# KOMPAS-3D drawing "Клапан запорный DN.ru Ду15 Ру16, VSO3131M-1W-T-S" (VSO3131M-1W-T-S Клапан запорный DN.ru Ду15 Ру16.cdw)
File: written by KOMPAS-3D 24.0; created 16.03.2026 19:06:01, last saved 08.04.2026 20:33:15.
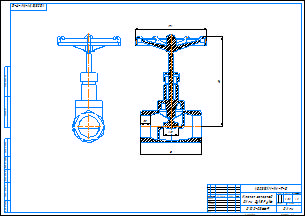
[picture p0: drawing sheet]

Document properties: c3d_UniqueCompID: 94d3474e-3e6e-4ddd-ad0b-ef51eb5e31da; Обозначение: VSO3131M-1W-T-S; Наименование: Клапан запорный DN.ru Ду15 Ру16; Материал: Сталь 10 ГОСТ 1050-2013; Автор: artiomk228874@gmail.com; Класс точности: c; Знак неуказанной шероховатости: Шероховатость не задана; Рассекать на разрезах: Да; Автор: artiomk228874@gmail.com; Форматы листов документа: A2; Полное имя файла: VSO3131M-1W-T-S Клапан запорный DN.ru Ду15 Ру16.m3d; Масса: 0.31; Наименование: Клапан запорный DN.ru Ду15 Ру16; Количество листов документа: 1; Примечание: D100-03669

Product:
- Body: Тело 1  | qty 1
    Масса: 0.243693
- Part/product: Клапан запорный DN.ru Ду15 Ру16  | designation VSO3131M-1W-T-S
    Масса: 0.31
    Раздел спецификации: Прочие изделия
    Форматы листов документа: A2
    Примечание: D100-03669
    additional columns: 94d3474e-3e6e-4ddd-ad0b-ef51eb5e31da; VSO3131M-1W-T-S; Сталь 10 ГОСТ 1050-2013; artiomk228874@gmail.com; c; Шероховатость не задана; Да

Views: Проекционный вид 2
Referenced files in C:\Users\artio\OneDrive\Рабочий стол\Клапан запорный DN.ru VSO3131M-1W-T-S Ду15-Ду50 Ру16\Ду15\: VSO3131M-1W-T-S Клапан запорный DN.ru Ду15 Ру16.m3d, VSO3131M-1W-T-S Клапан запорный DN.ru Ду15 Ру16.cdw
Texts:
  VSO3131M-1W-T-S
  Клапан запорный
  DN.ru Ду15 Ру16
  Клапан запорный DN.ru Ду15 Ру16
  VSO3131M-1W-T-S Клапан запорный DN.ru Ду15 Ру16
Dimensions and other numbers on the sheet: 0; 3; 4; 2:1; 1; 2; 0,31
